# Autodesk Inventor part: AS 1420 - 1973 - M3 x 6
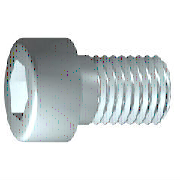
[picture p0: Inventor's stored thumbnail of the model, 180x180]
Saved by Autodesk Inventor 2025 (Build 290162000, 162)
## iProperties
IsCustomPart: 0
Created: 2024-01
Part Number: AS 1420 - 1973 - M3 x 6
Material: Acciaio, Dolce
Description: Viti con esagono incassato metriche ISO
Document SubType Name: Modeling
Standard: AS 1420 - 1973
Designer: R5800u
Standards Organization: AS
Language: it-IT
Size Designation: M3 x 6
Categories: <MemberInstance><Categories><Category DisplayName="Elementi di fissaggio" InternalName="e4da775c-781d-43d5-af7c-5136215cf5a6" Mnemonic="FSTN"><Category DisplayN
Density: 7.85 g/cm^3
Appearance: Semilucidato
Author: R5800u
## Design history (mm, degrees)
body "Solid1"
workplane "Work Plane1"
fillet "Fillet2" dims "d30" = 0.1 (= R)
revolve "Corpo" stored, may be unused: angle "d10" = 90 deg
sketch "Schizzo2"
  geometry: L1 (0, -3.85)-(0, 3.85) reference; L2 (-3.85, 0)-(3.85, 0) reference; L3 (1.443, 0)-(0.722, -1.25); L4 (0.722, -1.25)-(-0.722, -1.25); L5 (-0.722, -1.25)-(-1.443, 0); L6 (-1.443, 0)-(-0.722, 1.25); L7 (-0.722, 1.25)-(0.722, 1.25); L8 (0.722, 1.25)-(1.443, 0); 2 further points
  constraints: 12 end point, 1 coincident, 1 horizontal alignment, 1 point on line, 12 other
extrude "Intaglio" join sketch "Schizzo2" stored distance "d11" = 10; taper "d12" = 0 deg
fillet "Raccordo1" dims "d17" = 0.3 (= RR)
feature "Filettatura" dims "d13" = 4.75 (= GEL), "d14" = 0
chamfer "Smusso1" distance "d15" = 0.30673 (= -0.5 x SPD + 0.5 x GD); stored, may be unused: second distance "d16" = 0.30673 (= GUL), angle "d27" = 45 deg
sketch "Schizzo1"
  geometry: L1 (-0.867, 0)-(6, 0); L2 (6, 0)-(6, 1.5); L3 (6, 1.5)-(1.25, 1.5); L4 (1.25, 1.5)-(0.943, 1.5); L5 (0.943, 1.5)-(0, 1.5); L6 (0, 1.5)-(0, 2.75); L7 (0, 2.75)-(-3, 2.75); L8 (-3, 2.75)-(-3, 1.443); L9 (-3, 1.443)-(-1.7, 1.443); L10 (-1.7, 1.443)-(-0.867, 0); L11 (-4.8, 0)-(7.8, 0) reference; L12 (0, -0.55)-(0, 3.3) reference; L13 (1.25, 1.5)-(0, 1.5)
  constraints: 22 end point, 6 parallel, 2 collinear, 2 perpendicular, 1 horizontal, 1 point on line
  dimensions: "d1" = 4.75 distance from line of L3.end L2 (= GEL); "d2" = 0.30683 distance of L4.end L3.end (computed from GAL); "d3" = 3 distance between parallel lines of L8 L6 (= KOH); "d4" = 1.3 distance of L8.end L9.end (= INTI); "d5" = 60 deg angle of L10 L1; "d6" = 3 diameter of L3 L1 (= GD); "d7" = 3 diameter of L5 L1 (= BDM); "d8" = 2.88675 diameter of L9 L1 (= 1.1547 x SW); "d9" = 5.5 diameter of L7 L1 (= KOD); "d26" = 6 distance between parallel lines of L12 L2 (= NLG)
other parameters: "GD" = 3 (= NND) [user parameter; used in 2 equation terms], "NLG" = 6 [user parameter; used in 1 equation term], "GEL" = 4.75 [user parameter; used in 2 equation terms], "KOD" = 5.5 [user parameter; used in 1 equation term], "KOH" = 3 (= NND) [user parameter; used in 1 equation term], "INTI" = 1.3 [user parameter; used in 1 equation term], "GAL" = 0.30673 (= 0.61345 x PTC) [user parameter; used in 1 equation term], "GUL" = 0.30673 (= 0.61345 x PTC) [user parameter; used in 1 equation term], "BDM" = 3 (= NND) [user parameter; used in 1 equation term], "SW" = 2.5 [user parameter; used in 2 equation terms], "RR" = 0.3 (= 0.1 x NND) [user parameter; used in 1 equation term], "SPD" = 2.38655 (= NND - 1.2269 x PTC) [user parameter; used in 1 equation term], "d19" = 0, "d28" = 0, "d29" = 0, "R" = 0.1 [user parameter; used in 1 equation term], "PHH" = 0.13 [user parameter], "GD1" = 2.38655 (= THREADDIA - 1.2269 x PTC) [user parameter], "THREADDIA" = 3 [user parameter; used in 1 equation term], "FAWI" = 45 deg [user parameter], "PTC" = 0.5 [user parameter; used in 5 equation terms], "KOH1" = 2.7 [user parameter], "NND" = 3 [user parameter; used in 5 equation terms], "TOA" = 30 deg [user parameter], "E0" = 2.8875 (= 1.155 x SW) [user parameter]
